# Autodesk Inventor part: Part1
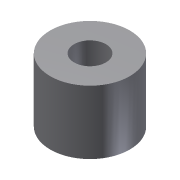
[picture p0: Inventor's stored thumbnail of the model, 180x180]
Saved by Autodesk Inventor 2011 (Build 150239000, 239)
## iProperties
Shininess: 77.0
Angle Display Precision: 2
Document Length Units: 11269
Document Angle Units: 11279
Document Time Units: 11290
Document Mass Units: 11283
Document Length Units Precision: 3
Document Angle Units Precision: 2
Created: 2002-01
Part Number: Part1
Document SubType Name: Modeling
Designer: ***
Density: 1 g/cm^3
Density: 0.0
Volumn: 0.0
Area: 0.0
PropertySet Name: Model Information
Control State: 0
Master: False
Checked Out: False
Author: ***
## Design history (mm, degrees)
sketch "Sketch1"
  geometry: C1 r 25 at (0, 0); C2 r 10 at (0, 0)
  constraints: 2 centre point, 1 coincident
  dimensions: "d0" = 50 diameter of C1; "d1" = 20 diameter of C2
extrude "Extrusion1" new body sketch "Sketch1" distance "d2" = 40; taper "d3" = 0 deg
body "Solid1"
